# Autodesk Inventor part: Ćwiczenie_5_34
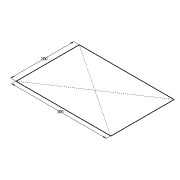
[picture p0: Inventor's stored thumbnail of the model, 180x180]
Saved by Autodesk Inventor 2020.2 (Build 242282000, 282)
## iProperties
Created: 2005-04
Part Number: Ćwiczenie_5_34
Document SubType Name: Modeling
Designer: F.Stasiak
Manufacturer: Standard
Standards Organization: Custom
Density: 1 g/cm^3
Material: Ogólny
Appearance: Domyślna
Manager: www.cadconsulting.pl
Company: Fabian Stasiak CAD Consulting
Author: F.Stasiak
Subject: Zbiór ćwiczeń. Autodesk Inventor 2020. Kurs podstawowy
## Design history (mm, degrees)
sketch "Szkic4"
  geometry: L1 (-150, -100)-(150, -100); L2 (150, -100)-(150, 100); L3 (150, 100)-(-150, 100); L4 (-150, 100)-(-150, -100); L5 (-150, -100)-(150, 100); L6 (150, -100)-(-150, 100); 1 further point
  constraints: 12 end point, 2 midpoint, 2 parallel, 1 horizontal, 1 perpendicular
  dimensions: "d9" = 300 dimension on point (0, 0) L1.start L2.end L1.end L3.end L1 L2 L3 L4 L5 L6; "d9" = 300 distance of L3.end L2.end; "d10" = 200 distance of L2.end L1.end
node "Korpusy bryłowe"
node "Korpusy powierzchniowe"
